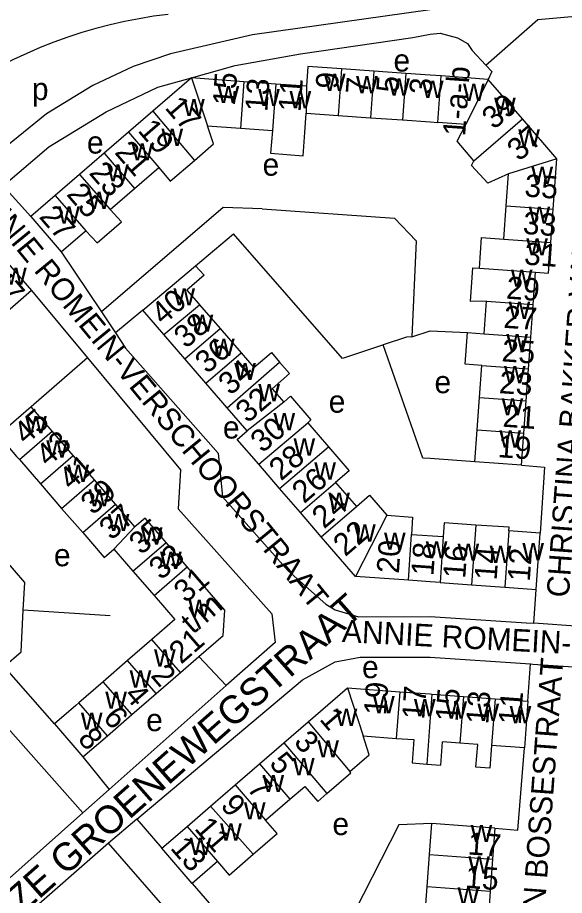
# Model space of a CAD drawing. Extents: x 159902 to 161769, y 383692 to 384875.
# Drawn here: x 160426.3 to 160524, y 383988.4 to 384145.4 of the extents above; entities that cross this region are included whole.
import ezdxf

# ---------------------------------------------------------------- set-up
doc = ezdxf.new("R2010")
doc.units = 0
for name, color, linetype in [('BLT_Basislijn', 7, 'Continuous'), ('BLT_Bebouwing', 7, 'Continuous'), ('BLT_Centroide', 7, 'Continuous'), ('BLT_Huisnummer', 7, 'Continuous'), ('BLT_Huisnummer_ tussenligend', 7, 'Continuous'), ('BLT_Huisnummer_reeks', 7, 'Continuous'), ('BLT_Onderverdeling_panden', 7, 'Continuous'), ('BLT_Straatnaam', 7, 'Continuous'), ('BLT_Straatnaam_verkleind', 7, 'Continuous')]:
    doc.layers.add(name, color=color, linetype=linetype)

msp = doc.modelspace()

# ---------------------------------------------------------------- linework, layer by layer
at = {"layer": 'BLT_Basislijn'}
for p, q in [((160428.64, 384109.85), (160423.68, 384115.34)), ((160458.06, 384101.04), (160464.87, 384106.75)), ((160434.08, 384103.54), (160441.26, 384092.79)), ((160428.73, 384096.58), (160438.74, 384084.56)), ((160441.26, 384092.79), (160443.76, 384089.03)), ((160448.65, 384093.1), (160443.76, 384089.03)), ((160438.74, 384084.56), (160428.67, 384075.8)), ((160518.54, 384037.11), (160518.94, 384043.15)), ((160442.83, 384038.42), (160427.29, 384039.41)), ((160458.66, 384031.15), (160463.54, 384025.97)), ((160432.87, 384019.1), (160423.86, 384029.39)), ((160517.48, 384023.16), (160517.93, 384029.81)), ((160463.54, 384025.97), (160442.65, 384007.38)), ((160437.94, 384003.19), (160418.62, 384024.93)), ((160437.95, 384013.22), (160442.65, 384007.38)), ((160442.65, 384007.38), (160437.94, 384003.19)), ((160437.94, 384003.19), (160421.53, 383988.6)), ((160447.59, 384002.05), (160442.51, 383997.79)), ((160447.59, 384002.05), (160452.05, 383996.88)), ((160442.51, 383997.79), (160423.34, 383980.97)), ((160462.31, 383975.11), (160442.51, 383997.79)), ((160457.49, 383990.58), (160467.2, 383979.33))]:
    msp.add_line(p, q, dxfattribs=at)
for points in [[(160513.4, 384148.33), (160500, 384146.79), (160468.24, 384142.34), (160453.61, 384138.94), (160446.91, 384136.68), (160439.69, 384133.26), (160431.46, 384128.18), (160423.21, 384121.53)], [(160509.95, 384136.94), (160519.25, 384145.08), (160536.04, 384146.55), (160541.6, 384140.66)], [(160453.18, 384146), (160450.58, 384145.65), (160447.98, 384145.22), (160445.39, 384144.72), (160442.83, 384144.13), (160440.28, 384143.47), (160437.75, 384142.73), (160435.24, 384141.91), (160432.77, 384141.02), (160430.32, 384140.05), (160427.9, 384139.01), (160425.51, 384137.9), (160423.16, 384136.71), (160420.85, 384135.46), (160418.57, 384134.13), (160416.34, 384132.74), (160414.94, 384131.8)], [(160457.33, 384134.64), (160465.15, 384136.84), (160476.84, 384138.91), (160496.89, 384141.85), (160500, 384142.46), (160501.81, 384142.61), (160504.88, 384141.82), (160506.7, 384140.8), (160507.5, 384139.52), (160509.95, 384136.94)], [(160509.95, 384136.94), (160511.07, 384135.76), (160510.39, 384134.37)], [(160423.68, 384115.34), (160431.85, 384122.32), (160442.09, 384128.59), (160451.36, 384132.96), (160457.33, 384134.64)], [(160469.96, 384111.22), (160462.99, 384111.48), (160441.26, 384092.79)], [(160469.96, 384111.22), (160493.65, 384109.54), (160497.53, 384105.48), (160496.74, 384088.3)], [(160491.61, 384086.87), (160491.31, 384086.77), (160484.32, 384084.46), (160464.87, 384106.75)], [(160443.76, 384089.03), (160445.58, 384086.3), (160462.13, 384067.52), (160462.92, 384059.68), (160474.61, 384046.5), (160481.36, 384040.52), (160483.05, 384039.5), (160487.18, 384038.22), (160500, 384038.33), (160517.18, 384037.2), (160518.54, 384037.11)], [(160496.74, 384088.3), (160495.76, 384088.29), (160491.61, 384086.87)], [(160496.74, 384088.3), (160500, 384089.39), (160506.71, 384089.1)], [(160508.01, 384065.96), (160500, 384066.56), (160498.71, 384066.65), (160491.61, 384086.87)], [(160438.74, 384084.56), (160455.41, 384064.55), (160454.98, 384057.56), (160471.74, 384038.77), (160472.32, 384033.68), (160463.54, 384025.97)], [(160516.37, 384065.36), (160520.44, 384064.99), (160519.66, 384053.23)], [(160427.29, 384039.41), (160427.55, 384044.41), (160412.72, 384061.55)], [(160423.86, 384029.39), (160426.91, 384031.99), (160427.29, 384039.41)], [(160527.14, 384036.5), (160526.83, 384036.52), (160518.54, 384037.11)], [(160447.59, 384002.05), (160477.22, 384026.96), (160483.05, 384030.18), (160487.5, 384031.05), (160500, 384031.03), (160517.93, 384029.81)], [(160517.93, 384029.81), (160518.36, 384029.79), (160526.52, 384029.24)], [(160511.59, 384000.44), (160515.71, 384000.09), (160516.87, 384014.82)], [(160500.3, 384001.27), (160494.44, 384001.03), (160484.96, 383982.42)]]:
    msp.add_lwpolyline(points, dxfattribs=at)
at = {"layer": 'BLT_Bebouwing'}
for p, q in [((160489.93, 384135.84), (160484.19, 384136.25)), ((160495.68, 384135.43), (160489.93, 384135.84)), ((160457.33, 384134.64), (160450.45, 384128.68)), ((160466.69, 384133.94), (160457.33, 384134.64)), ((160472.44, 384133.53), (160466.69, 384133.94)), ((160477.91, 384133.14), (160472.44, 384133.53)), ((160510.39, 384134.37), (160502, 384134.98)), ((160516.5, 384127.29), (160510.39, 384134.37)), ((160450.45, 384128.68), (160446.09, 384124.91)), ((160477.84, 384128.35), (160483.59, 384127.93)), ((160483.59, 384127.93), (160489.34, 384127.52)), ((160489.34, 384127.52), (160495.09, 384127.11)), ((160522.65, 384120.16), (160516.5, 384127.29)), ((160460.2, 384126.09), (160466.1, 384125.66)), ((160466.1, 384125.66), (160471.84, 384125.25)), ((160506.4, 384126.3), (160501.4, 384126.66)), ((160446.09, 384124.91), (160441.73, 384121.15)), ((160441.73, 384121.15), (160437.36, 384117.38)), ((160522.01, 384111.13), (160522.65, 384120.16)), ((160447.17, 384114.84), (160451.53, 384118.6)), ((160437.36, 384117.38), (160433, 384113.62)), ((160513.63, 384111.74), (160514.04, 384117.45)), ((160442.81, 384111.07), (160447.17, 384114.84)), ((160433, 384113.62), (160428.64, 384109.85)), ((160513.2, 384105.78), (160513.63, 384111.74)), ((160521.58, 384105.17), (160522.01, 384111.13)), ((160428.64, 384109.85), (160434.08, 384103.54)), ((160521.19, 384099.71), (160521.58, 384105.17)), ((160423.74, 384102.42), (160428.73, 384096.58)), ((160448.65, 384093.1), (160458.06, 384101.04)), ((160518.43, 384094.12), (160518.84, 384099.87)), ((160518.84, 384099.87), (160521.19, 384099.71)), ((160509.65, 384088.88), (160510.07, 384094.72)), ((160452.41, 384088.74), (160448.65, 384093.1)), ((160458.8, 384094.05), (160462.46, 384089.8)), ((160518.01, 384088.25), (160518.43, 384094.12)), ((160462.46, 384089.8), (160466.23, 384085.44)), ((160456.17, 384084.38), (160452.41, 384088.74)), ((160506.71, 384089.1), (160509.65, 384088.88)), ((160517.6, 384082.62), (160518.01, 384088.25)), ((160459.94, 384080.01), (160456.17, 384084.38)), ((160508.84, 384077.46), (160509.25, 384083.22)), ((160517.19, 384076.86), (160517.6, 384082.62)), ((160463.7, 384075.65), (160459.94, 384080.01)), ((160508.42, 384071.71), (160508.84, 384077.46)), ((160428.67, 384075.8), (160422.81, 384070.72)), ((160432.45, 384071.44), (160428.67, 384075.8)), ((160467.28, 384071.5), (160463.7, 384075.65)), ((160516.78, 384071.11), (160517.19, 384076.86)), ((160478.13, 384072.96), (160481.84, 384068.66)), ((160436.22, 384067.09), (160432.45, 384071.44)), ((160508.01, 384065.96), (160508.42, 384071.71)), ((160516.37, 384065.36), (160516.78, 384071.11)), ((160426.58, 384066.37), (160430.35, 384062.01)), ((160439.99, 384062.73), (160436.22, 384067.09)), ((160473.08, 384061.2), (160469.4, 384065.56)), ((160430.35, 384062.01), (160434.12, 384057.65)), ((160443.76, 384058.37), (160439.99, 384062.73)), ((160483.12, 384062.28), (160486.83, 384057.98)), ((160476.81, 384056.89), (160473.08, 384061.2)), ((160447.24, 384054.35), (160443.76, 384058.37)), ((160434.12, 384057.65), (160437.9, 384053.3)), ((160480.54, 384052.57), (160476.81, 384056.89)), ((160492.29, 384056.41), (160496.88, 384056.08)), ((160486.66, 384045.47), (160480.54, 384052.57)), ((160518.94, 384043.15), (160519.66, 384053.23)), ((160443.49, 384050.34), (160446.88, 384046.42)), ((160456.58, 384047.2), (160452.81, 384051.55)), ((160446.88, 384046.42), (160450.65, 384042.07)), ((160496.14, 384044.79), (160486.66, 384045.47)), ((160501.81, 384044.38), (160507.41, 384043.98)), ((160507.41, 384043.98), (160513.35, 384043.55)), ((160513.35, 384043.55), (160518.94, 384043.15)), ((160450.29, 384034.18), (160445.94, 384030.41)), ((160445.94, 384030.41), (160441.58, 384026.64)), ((160455.38, 384028.31), (160458.66, 384031.15)), ((160451.02, 384024.54), (160455.38, 384028.31)), ((160441.58, 384026.64), (160437.22, 384022.87)), ((160478.21, 384019.48), (160485.22, 384025.53)), ((160485.22, 384025.53), (160494.6, 384024.84)), ((160446.67, 384020.76), (160451.02, 384024.54)), ((160500.34, 384024.42), (160505.97, 384024.01)), ((160505.97, 384024.01), (160511.65, 384023.59)), ((160511.65, 384023.59), (160517.48, 384023.16)), ((160517.48, 384023.16), (160516.87, 384014.82)), ((160442.31, 384016.99), (160446.67, 384020.76)), ((160432.87, 384019.1), (160437.95, 384013.22)), ((160473.85, 384015.71), (160478.21, 384019.48)), ((160437.95, 384013.22), (160442.31, 384016.99)), ((160488.05, 384016.94), (160493.96, 384016.51)), ((160505.31, 384015.67), (160502.21, 384015.9)), ((160469.49, 384011.95), (160473.85, 384015.71)), ((160516.87, 384014.82), (160510.99, 384015.25)), ((160465.13, 384008.18), (160469.49, 384011.95)), ((160460.77, 384004.41), (160465.13, 384008.18)), ((160470.59, 384001.86), (160474.95, 384005.63)), ((160456.56, 384000.77), (160460.77, 384004.41)), ((160511.59, 384000.44), (160511.18, 383994.89)), ((160499.47, 383990.04), (160499.89, 383995.74)), ((160511.18, 383994.89), (160510.76, 383989.2)), ((160510.76, 383989.2), (160510.34, 383983.5))]:
    msp.add_line(p, q, dxfattribs=at)
for points in [[(160484.19, 384136.25), (160478.17, 384136.68), (160477.91, 384133.14)], [(160502, 384134.98), (160500, 384135.12), (160495.68, 384135.43)], [(160471.84, 384125.25), (160471.45, 384121.2), (160477.29, 384120.71), (160477.59, 384124.84), (160477.84, 384128.35)], [(160457.87, 384119.88), (160461.28, 384122.83), (160460.2, 384126.09)], [(160495.09, 384127.11), (160500, 384126.76), (160501.4, 384126.66)], [(160507.85, 384119.83), (160504.85, 384123.3), (160506.4, 384126.3)], [(160451.53, 384118.6), (160453.56, 384116.17), (160457.87, 384119.88)], [(160514.04, 384117.45), (160510.3, 384115.83), (160507.38, 384118.99), (160507.85, 384119.83)], [(160438.44, 384107.31), (160440.51, 384105.16), (160444.81, 384108.88), (160442.81, 384111.07)], [(160434.08, 384103.54), (160437.87, 384106.81), (160438.44, 384107.31)], [(160508.82, 384100.59), (160509.21, 384106.07), (160513.2, 384105.78)], [(160458.06, 384101.04), (160459.61, 384099.34), (160456.53, 384096.68), (160458.55, 384094.34), (160458.8, 384094.05)], [(160510.07, 384094.72), (160507.2, 384094.63), (160507.63, 384100.68), (160508.82, 384100.59)], [(160428.73, 384096.58), (160424.95, 384093.3), (160424.38, 384092.81)], [(160509.25, 384083.22), (160506.3, 384083.41), (160506.71, 384089.1)], [(160466.23, 384085.44), (160468.49, 384082.81), (160471.64, 384085.53), (160473.11, 384083.82)], [(160473.11, 384083.82), (160474.9, 384081.74), (160471.76, 384079.03), (160473.83, 384076.63)], [(160473.83, 384076.63), (160475.06, 384077.69), (160478.71, 384073.46), (160478.13, 384072.96)], [(160422.81, 384070.72), (160426.08, 384066.94), (160426.58, 384066.37)], [(160469.4, 384065.56), (160465.52, 384069.97), (160467.28, 384071.5)], [(160481.84, 384068.66), (160485.55, 384064.37), (160483.12, 384062.28)], [(160516.37, 384065.36), (160511.38, 384065.72), (160508.01, 384065.96)], [(160486.83, 384057.98), (160489.18, 384060.01), (160492.29, 384056.41)], [(160452.81, 384051.55), (160449.04, 384055.91), (160447.24, 384054.35)], [(160496.88, 384056.08), (160496.66, 384053)], [(160508.19, 384054.66), (160502.5, 384055.04), (160502.34, 384052.59)], [(160514.08, 384053.63), (160514.11, 384054.26), (160508.19, 384054.66)], [(160519.66, 384053.23), (160514.08, 384053.63)], [(160437.9, 384053.3), (160441.76, 384048.84), (160443.49, 384050.34)], [(160496.66, 384053), (160502.34, 384052.59)], [(160458.66, 384031.15), (160463, 384034.91), (160463.32, 384039.41), (160456.58, 384047.2)], [(160501.81, 384044.38), (160500, 384044.51), (160496.14, 384044.79)], [(160450.65, 384042.07), (160454.4, 384037.74), (160450.29, 384034.18)], [(160494.6, 384024.84), (160500, 384024.45), (160500.34, 384024.42)], [(160437.22, 384022.87), (160436.65, 384022.37), (160432.87, 384019.1)], [(160485.65, 384010.59), (160489.12, 384013.59), (160488.05, 384016.94)], [(160493.96, 384016.51), (160497.1, 384016.28), (160496.81, 384012.11), (160499.43, 384011.91)], [(160499.43, 384011.91), (160501.9, 384011.73), (160502.21, 384015.9)], [(160510.99, 384015.25), (160510.67, 384011.16), (160508.21, 384011.36), (160508.53, 384015.43), (160505.31, 384015.67)], [(160481.52, 384006.62), (160485.85, 384010.36), (160485.65, 384010.59)], [(160474.95, 384005.63), (160477.59, 384007.92), (160479.91, 384005.23), (160481.52, 384006.62)], [(160468.38, 383995.78), (160472.68, 383999.49), (160470.59, 384001.86)], [(160452.05, 383996.88), (160456.56, 384000.77)], [(160499.89, 383995.74), (160500.3, 384001.27)], [(160511.59, 384000.44), (160506.6, 384000.81), (160500.3, 384001.27)], [(160457.49, 383990.58), (160452.05, 383996.88)], [(160462, 383994.47), (160464.07, 383992.06), (160468.38, 383995.78)], [(160462, 383994.47), (160457.49, 383990.58)], [(160499.06, 383984.36), (160499.47, 383990.04)]]:
    msp.add_lwpolyline(points, dxfattribs=at)
at = {"layer": 'BLT_Onderverdeling_panden'}
for p, q in [((160484.19, 384136.25), (160483.59, 384127.93)), ((160489.93, 384135.84), (160489.34, 384127.52)), ((160495.68, 384135.43), (160495.09, 384127.11)), ((160457.33, 384134.64), (160460.2, 384126.09)), ((160466.69, 384133.94), (160466.1, 384125.66)), ((160472.44, 384133.53), (160471.84, 384125.25)), ((160501.4, 384126.66), (160502, 384134.98)), ((160510.39, 384134.37), (160506.4, 384126.3)), ((160477.91, 384133.14), (160477.84, 384128.35)), ((160450.45, 384128.68), (160457.87, 384119.88)), ((160507.85, 384119.83), (160516.5, 384127.29)), ((160446.09, 384124.91), (160451.53, 384118.6)), ((160441.73, 384121.15), (160447.17, 384114.84)), ((160522.65, 384120.16), (160514.04, 384117.45)), ((160437.36, 384117.38), (160442.81, 384111.07)), ((160433, 384113.62), (160438.44, 384107.31)), ((160513.63, 384111.74), (160522.01, 384111.13)), ((160513.2, 384105.78), (160521.58, 384105.17)), ((160508.82, 384100.59), (160518.84, 384099.87)), ((160510.07, 384094.72), (160518.43, 384094.12)), ((160452.41, 384088.74), (160458.8, 384094.05)), ((160456.17, 384084.38), (160462.46, 384089.8)), ((160509.65, 384088.88), (160518.01, 384088.25)), ((160459.94, 384080.01), (160466.23, 384085.44)), ((160463.7, 384075.65), (160473.11, 384083.82)), ((160509.25, 384083.22), (160517.6, 384082.62)), ((160508.84, 384077.46), (160517.19, 384076.86)), ((160473.83, 384076.63), (160467.28, 384071.5)), ((160469.4, 384065.56), (160478.13, 384072.96)), ((160426.58, 384066.37), (160432.45, 384071.44)), ((160508.42, 384071.71), (160516.78, 384071.11)), ((160473.08, 384061.2), (160481.84, 384068.66)), ((160430.35, 384062.01), (160436.22, 384067.09)), ((160434.12, 384057.65), (160439.99, 384062.73)), ((160476.81, 384056.89), (160483.12, 384062.28)), ((160437.9, 384053.3), (160443.76, 384058.37)), ((160480.54, 384052.57), (160486.83, 384057.98)), ((160492.29, 384056.41), (160486.66, 384045.47)), ((160447.24, 384054.35), (160443.49, 384050.34)), ((160508.19, 384054.66), (160507.41, 384043.98)), ((160514.08, 384053.63), (160513.35, 384043.55)), ((160496.14, 384044.79), (160496.66, 384053)), ((160502.34, 384052.59), (160501.81, 384044.38)), ((160446.88, 384046.42), (160452.81, 384051.55)), ((160450.65, 384042.07), (160456.58, 384047.2)), ((160455.38, 384028.31), (160450.29, 384034.18)), ((160451.02, 384024.54), (160445.94, 384030.41)), ((160446.67, 384020.76), (160441.58, 384026.64)), ((160485.22, 384025.53), (160488.05, 384016.94)), ((160494.6, 384024.84), (160493.96, 384016.51)), ((160500.34, 384024.42), (160499.43, 384011.91)), ((160505.97, 384024.01), (160505.31, 384015.67)), ((160511.65, 384023.59), (160510.99, 384015.25)), ((160442.31, 384016.99), (160437.22, 384022.87)), ((160478.21, 384019.48), (160485.65, 384010.59)), ((160473.85, 384015.71), (160481.52, 384006.62)), ((160469.49, 384011.95), (160474.95, 384005.63)), ((160465.13, 384008.18), (160470.59, 384001.86)), ((160460.77, 384004.41), (160468.38, 383995.78)), ((160456.56, 384000.77), (160462, 383994.47)), ((160499.89, 383995.74), (160511.18, 383994.89)), ((160499.47, 383990.04), (160510.76, 383989.2))]:
    msp.add_line(p, q, dxfattribs=at)

# ---------------------------------------------------------------- texts
at = {"layer": 'BLT_Centroide'}
for s, p in [('e', (160493.46, 384135.77)), ('w', (160481.02, 384132.3)), ('p', (160428.82, 384130.67)), ('w', (160486.77, 384131.89)), ('w', (160492.52, 384131.47)), ('w', (160498.55, 384131.05)), ('w', (160505.89, 384130.52)), ('w', (160462.02, 384130.12)), ('w', (160469.27, 384129.59)), ('w', (160474.88, 384129.19)), ('w', (160455.86, 384127.81)), ('w', (160511.45, 384128.03)), ('e', (160438.66, 384121.1)), ('w', (160451.98, 384122.47)), ('w', (160515.77, 384122.38)), ('w', (160446.62, 384119.88)), ('e', (160470.06, 384117.14)), ('w', (160442.27, 384116.11)), ('w', (160518.12, 384115.66)), ('w', (160438.91, 384111.2)), ('w', (160433.53, 384108.58)), ('w', (160517.62, 384108.56)), ('w', (160517.2, 384102.88)), ('w', (160424.03, 384097.64)), ('w', (160514.45, 384097.28)), ('w', (160454.12, 384093.94)), ('w', (160514.05, 384091.53)), ('w', (160457.38, 384089.22)), ('w', (160461.2, 384084.91)), ('w', (160513.63, 384085.78)), ('w', (160465, 384080.59)), ('w', (160513.22, 384080.03)), ('e', (160500.79, 384078.24)), ('w', (160469.3, 384076.8)), ('e', (160481.88, 384074.76)), ('w', (160512.8, 384074.28)), ('w', (160427.62, 384071.09)), ('w', (160472.01, 384071.62)), ('e', (160462.97, 384070.13)), ('w', (160512.39, 384068.53)), ('w', (160431.4, 384066.72)), ('w', (160475.59, 384067.09)), ('w', (160435.17, 384062.38)), ('w', (160479.31, 384062.78)), ('w', (160438.95, 384058)), ('w', (160481.81, 384057.41)), ('w', (160442.39, 384053.59)), ('w', (160448.31, 384051.16)), ('w', (160486.41, 384051.69)), ('w', (160491.77, 384050.25)), ('e', (160432.76, 384047.29)), ('w', (160499.23, 384048.69)), ('w', (160504.91, 384048.28)), ('w', (160510.67, 384047.88)), ('w', (160516.5, 384048.38)), ('w', (160451.73, 384046.81)), ('w', (160456.81, 384038.23)), ('w', (160450.66, 384029.36)), ('e', (160487.84, 384027.28)), ('w', (160446.3, 384025.59)), ('w', (160441.94, 384021.81)), ('w', (160489.81, 384021)), ('w', (160497.12, 384020.47)), ('w', (160502.75, 384020.06)), ('w', (160508.48, 384019.62)), ('w', (160514.23, 384019.22)), ('w', (160437.59, 384018.05)), ('e', (160449.25, 384017.8)), ('w', (160483.12, 384018.75)), ('w', (160479.84, 384013.09)), ('w', (160475.5, 384009.92)), ('w', (160470.05, 384006.91)), ('w', (160466.73, 384002)), ('e', (160482.55, 383999.21)), ('w', (160462.47, 383998.22)), ('w', (160507.25, 383997.97)), ('w', (160457.03, 383995.67)), ('w', (160506.84, 383992.34)), ('w', (160504.91, 383986.78))]:
    msp.add_text(s, height=4, dxfattribs=at).set_placement(p)
at = {"layer": 'BLT_Huisnummer'}
for s, rotation, p in [('15', 85.8948, (160465.11, 384129.57)), ('9', 85.8948, (160483.51, 384132.57)), ('5', 85.8948, (160494.34, 384131.9)), ('17', 310.7907, (160452.44, 384129.25)), ('39', 40.7842, (160511.43, 384125.26)), ('21', 310.7907, (160443.46, 384121.24)), ('35', 355.8964, (160516.79, 384113.43)), ('27', 310.7907, (160429.97, 384109.73)), ('31', 355.9032, (160516.73, 384101.26)), ('47', 310.5212, (160420.93, 384098.39)), ('40', 40.7928, (160452.28, 384090.29)), ('27', 355.8993, (160513.04, 384089.95)), ('36', 40.7876, (160460.15, 384081.58)), ('23', 355.8998, (160512.25, 384078.26)), ('32', 40.7937, (160467.39, 384072.75)), ('45', 40.885, (160427.72, 384068.89)), ('19', 355.9054, (160512.02, 384066.81)), ('28', 40.7937, (160473.37, 384062.44)), ('41', 40.8801, (160435.81, 384060.74)), ('24', 40.7937, (160481.04, 384053.86)), ('37', 40.8801, (160443.02, 384051.8)), ('20', 85.8949, (160494.42, 384045.9)), ('33', 40.882, (160451.91, 384044.69)), ('16', 85.8948, (160506.28, 384045.02)), ('12', 85.8948, (160517.82, 384044.47)), ('2', 310.8836, (160449.91, 384027.67)), ('19', 85.8026, (160492.13, 384020.55)), ('15', 85.8099, (160504.93, 384019.41)), ('11', 85.8025, (160516.21, 384018.86)), ('1', 310.8328, (160480.08, 384019.88)), ('8', 310.8836, (160436.86, 384016.32)), ('5', 310.8328, (160471.1, 384011.93)), ('9', 310.8326, (160462.39, 384004.4)), ('13', 311.1224, (160453.42, 383996.83)), ('17', 355.7903, (160506.64, 383995.76))]:
    msp.add_text(s, height=4, rotation=rotation, dxfattribs=at).set_placement(p)
at = {"layer": 'BLT_Huisnummer_ tussenligend'}
for s, rotation, p in [('13', 85.8948, (160470.9, 384128.5)), ('11', 85.8948, (160476.85, 384128.48)), ('7', 85.8948, (160488.89, 384131.64)), ('3', 85.8948, (160500.25, 384131.56)), ('19', 310.7907, (160447.61, 384125.16)), ('37', 40.7842, (160515.92, 384119.57)), ('23', 310.7907, (160438.9, 384117.55)), ('25', 310.7907, (160434.87, 384113.75)), ('33', 355.9032, (160516.51, 384106.75)), ('29', 355.8993, (160513.52, 384095.16)), ('38', 40.7876, (160456.37, 384086.09)), ('25', 355.8998, (160512.72, 384083.95)), ('34', 40.7937, (160464.3, 384077.72)), ('21', 355.9054, (160512.9, 384072.26)), ('30', 40.7937, (160470.05, 384067.42)), ('43', 40.8801, (160431.68, 384064.95)), ('26', 40.7937, (160477.48, 384058.37)), ('39', 40.8801, (160439.71, 384056.32)), ('35', 40.882, (160448.36, 384049.19)), ('22', 40.7937, (160484.84, 384048.9)), ('18', 85.8948, (160500.59, 384045.5)), ('14', 85.8948, (160511.89, 384044.69)), ('4', 310.8836, (160445.17, 384024.13)), ('17', 85.8099, (160498.95, 384019.8)), ('13', 85.8025, (160510.4, 384018.94)), ('6', 310.8836, (160441.38, 384020.1)), ('3', 310.8328, (160475.49, 384015.76)), ('7', 310.8328, (160467.12, 384007.47)), ('11', 310.8326, (160457.73, 384000.33)), ('15', 355.7879, (160506.19, 383989.79))]:
    msp.add_text(s, height=4, rotation=rotation, dxfattribs=at).set_placement(p)
at = {"layer": 'BLT_Huisnummer_reeks'}
for s, rotation, p in [('1-a-b', 85.8948, (160506.26, 384124.13)), ('31', 40.885, (160456.35, 384040.57)), ('t/m', 40.8851, (160457.61, 384035.01)), ('21', 40.8851, (160455.5, 384029.66))]:
    msp.add_text(s, height=4, rotation=rotation, dxfattribs=at).set_placement(p)
at = {"layer": 'BLT_Straatnaam'}
msp.add_text('SUZE GROENEWEGSTRAAT', height=5, rotation=41.4257, dxfattribs=at).set_placement((160420.04, 383978.77))
at = {"layer": 'BLT_Straatnaam_verkleind'}
for s, rotation, p in [('CHRISTINA BAKKER-VAN BOSSESTRAAT', 85.7906, (160524.8, 384041.61)), ('ANNIE ROMEIN-VERSCHOORSTRAAT', 309.378, (160417.73, 384113.93)), ('ANNIE ROMEIN-VERSCHOORSTRAAT', 356.9549, (160484.19, 384033.75)), ('CHRISTINA BAKKER-VAN BOSSESTRAAT', 85.7906, (160516.05, 383925.23))]:
    msp.add_text(s, height=4, rotation=rotation, dxfattribs=at).set_placement(p)

doc.saveas('drawing.dxf')
